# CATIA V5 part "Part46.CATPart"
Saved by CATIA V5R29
Part number: Aluminum case
Revision: ANY
Definition: UNKNOWN
Nomenclature: Aluminum case
Source: Unknown
Bounding box of the stored display mesh (mm): x 0 to 42, y 0 to 200, z -22 to 22
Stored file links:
  C:\Users\Administrator\Desktop\프로젝트\Gripper\Part46.CATPart
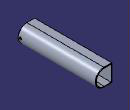
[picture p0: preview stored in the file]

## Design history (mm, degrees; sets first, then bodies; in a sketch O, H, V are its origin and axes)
Body1 "Cut-Extrude1" (main body)
  Solid1: solid without history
